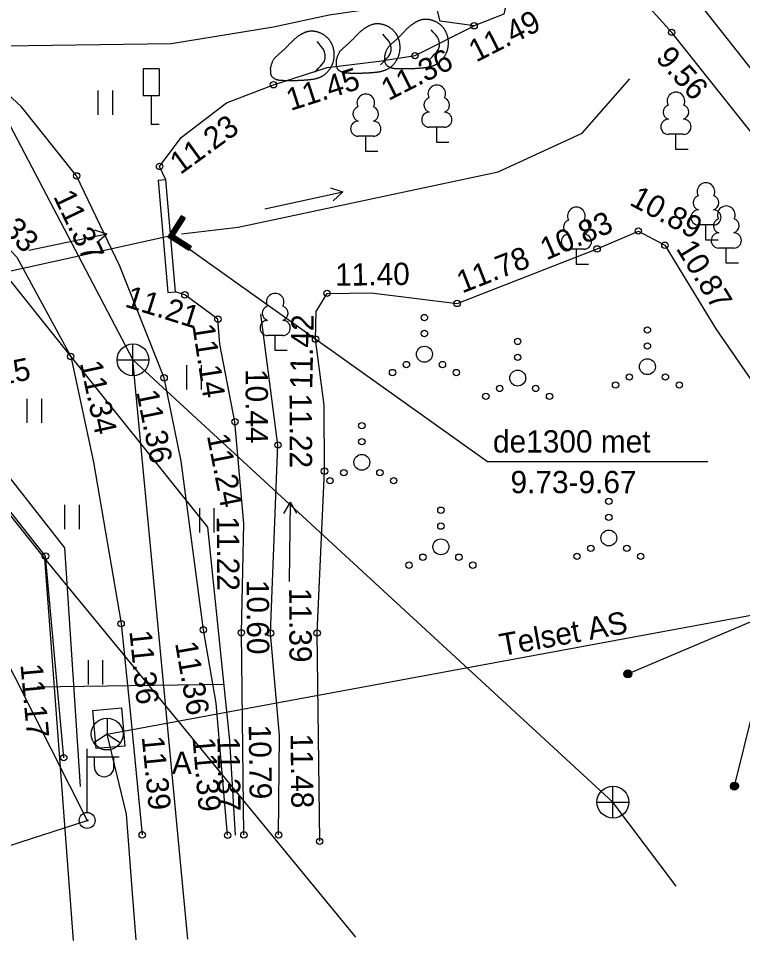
# Model space of a CAD drawing. Extents: x 554198 to 554371, y 6593448 to 6593563.
# Drawn here: x 554259.39 to 554282.11, y 6593473.51 to 6593502.46 of the extents above; entities that cross this region are included whole.
import ezdxf

# ---------------------------------------------------------------- set-up
doc = ezdxf.new("R2010")
doc.units = 0
for name, color, linetype in [('AED', 7, 'Continuous'), ('HALJASTUS', 7, 'Continuous'), ('KKAEV', 7, 'Continuous'), ('KORGUS-EH2000', 7, 'Continuous'), ('KTRASS', 7, 'Continuous'), ('LIIKLUS', 7, 'Continuous'), ('MPOHULIIN', 7, 'Continuous'), ('PIIR', 7, 'Continuous'), ('POST', 7, 'Continuous'), ('PUU', 7, 'Continuous'), ('RELJEEF', 7, 'Continuous'), ('SIKAEV', 7, 'Continuous'), ('SITRASS', 7, 'Continuous'), ('TEE', 7, 'Continuous'), ('TRUUP', 7, 'Continuous'), ('VEEKOGU', 7, 'Continuous'), ('VTRASS', 7, 'Continuous')]:
    doc.layers.add(name, color=color, linetype=linetype)

msp = doc.modelspace()

# ---------------------------------------------------------------- linework, layer by layer
at = {"layer": 'AED'}
msp.add_lwpolyline([(554260.808, 6593479.255), (554260.236, 6593485.581), (554256.809, 6593489.922), (554255.799, 6593491.136), (554253.28, 6593490.558), (554237.91, 6593487.208)], dxfattribs=at)
at = {"layer": 'HALJASTUS'}
for p, q in [((554261.882, 6593500.196), (554261.882, 6593499.435)), ((554262.337, 6593500.196), (554262.337, 6593499.435)), ((554264.664, 6593491.571), (554264.664, 6593490.81)), ((554265.119, 6593491.571), (554265.119, 6593490.81)), ((554259.652, 6593490.523), (554259.652, 6593489.761)), ((554260.107, 6593490.523), (554260.107, 6593489.761)), ((554260.837, 6593487.189), (554260.837, 6593486.428)), ((554261.292, 6593487.189), (554261.292, 6593486.428)), ((554265.065, 6593487.083), (554265.065, 6593486.321)), ((554265.52, 6593487.083), (554265.52, 6593486.321)), ((554261.57, 6593482.312), (554261.57, 6593481.551)), ((554262.025, 6593482.312), (554262.025, 6593481.551))]:
    msp.add_line(p, q, dxfattribs=at)
msp.add_lwpolyline([(554257.157, 6593490.52), (554260.832, 6593485.839), (554261.325, 6593478.347)], dxfattribs=at)
for centre, radius in [((554272.125, 6593493.069), 0.1), ((554272.125, 6593492.569), 0.1), ((554279.122, 6593492.678), 0.1), ((554275.052, 6593492.321), 0.1), ((554272.125, 6593491.919), 0.25), ((554279.122, 6593492.178), 0.1), ((554275.052, 6593491.821), 0.1), ((554279.122, 6593491.528), 0.25), ((554271.125, 6593491.344), 0.1), ((554271.56, 6593491.594), 0.1), ((554272.69, 6593491.594), 0.1), ((554273.125, 6593491.344), 0.1), ((554275.052, 6593491.171), 0.25), ((554278.557, 6593491.203), 0.1), ((554279.687, 6593491.203), 0.1), ((554274.487, 6593490.846), 0.1), ((554275.617, 6593490.846), 0.1), ((554278.122, 6593490.953), 0.1), ((554280.122, 6593490.953), 0.1), ((554274.052, 6593490.596), 0.1), ((554276.052, 6593490.596), 0.1), ((554270.162, 6593489.676), 0.1), ((554270.162, 6593489.176), 0.1), ((554270.162, 6593488.526), 0.25), ((554269.597, 6593488.201), 0.1), ((554270.727, 6593488.201), 0.1), ((554269.162, 6593487.951), 0.1), ((554271.162, 6593487.951), 0.1), ((554277.912, 6593487.301), 0.1), ((554272.642, 6593487.023), 0.1), ((554277.912, 6593486.801), 0.1), ((554272.642, 6593486.523), 0.1), ((554277.912, 6593486.151), 0.25), ((554272.642, 6593485.873), 0.25), ((554277.347, 6593485.826), 0.1), ((554278.477, 6593485.826), 0.1), ((554272.077, 6593485.548), 0.1), ((554273.207, 6593485.548), 0.1), ((554276.912, 6593485.576), 0.1), ((554278.912, 6593485.576), 0.1), ((554271.642, 6593485.298), 0.1), ((554273.642, 6593485.298), 0.1)]:
    msp.add_circle(centre, radius, dxfattribs=at)
at = {"layer": 'KKAEV'}
for p, q in [((554262.98, 6593491.24), (554262.98, 6593492.24)), ((554262.48, 6593491.74), (554263.48, 6593491.74)), ((554278.04, 6593477.36), (554278.04, 6593478.36)), ((554277.54, 6593477.86), (554278.54, 6593477.86))]:
    msp.add_line(p, q, dxfattribs=at)
for centre in [(554262.98, 6593491.74), (554278.04, 6593477.86)]:
    msp.add_circle(centre, 0.5, dxfattribs=at)
at = {"layer": 'KORGUS-EH2000'}
for centre in [(554273.684, 6593502.229), (554279.884, 6593502.023), (554271.831, 6593501.292), (554267.388, 6593500.378), (554263.816, 6593497.814), (554261.213, 6593497.518), (554278.839, 6593495.787), (554277.543, 6593495.225), (554279.67, 6593495.34), (554264.61, 6593493.783), (554269.07, 6593493.83), (554273.152, 6593493.512), (554265.646, 6593493.019), (554268.71, 6593492.39), (554261.027, 6593491.848), (554263.957, 6593491.18), (554266.18, 6593489.8), (554267.53, 6593489.07), (554268.99, 6593488.25), (554260.236, 6593485.581), (554262.608, 6593483.462), (554265.19, 6593483.27), (554266.381, 6593483.176), (554267.298, 6593483.162), (554268.76, 6593483.17), (554260.808, 6593479.255), (554263.27, 6593476.83), (554265.95, 6593476.82), (554266.46, 6593476.83), (554267.55, 6593476.83), (554268.84, 6593476.63)]:
    msp.add_circle(centre, 0.1, dxfattribs=at)
at = {"layer": 'KTRASS'}
for points in [[(554255.375, 6593506.25), (554262.98, 6593491.74)], [(554264.698, 6593473.559), (554262.98, 6593491.74)], [(554262.98, 6593491.74), (554278.04, 6593477.86)], [(554280.029, 6593475.225), (554278.04, 6593477.86)]]:
    msp.add_lwpolyline(points, dxfattribs=at)
at = {"layer": 'LIIKLUS'}
for points in [[(554263.305, 6593500.88), (554263.305, 6593500.03)], [(554263.805, 6593500.88), (554263.305, 6593500.88)], [(554263.805, 6593500.88), (554263.805, 6593500.03)], [(554263.805, 6593500.03), (554263.305, 6593500.03)], [(554263.555, 6593500.03), (554263.555, 6593499.13)], [(554263.805, 6593499.13), (554263.555, 6593499.13)]]:
    msp.add_lwpolyline(points, dxfattribs=at)
at = {"layer": 'MPOHULIIN'}
msp.add_lwpolyline([(554248.452, 6593503.231), (554261.544, 6593477.284)], dxfattribs=at)
at = {"layer": 'PIIR'}
for p, q in [((554294.582, 6593485.373), (554263.353, 6593525.033)), ((554255.79, 6593491.05), (554260.2, 6593485.51)), ((554260.2, 6593485.51), (554261.101, 6593473.514)), ((554260.2, 6593485.51), (554269.962, 6593473.624))]:
    msp.add_line(p, q, dxfattribs=at)
at = {"layer": 'POST'}
for p, q in [((554278.509, 6593481.885), (554283.22, 6593483.889)), ((554281.851, 6593478.362), (554283.22, 6593483.889)), ((554261.544, 6593477.534), (554261.544, 6593479.534)), ((554261.544, 6593479.284), (554262.544, 6593479.284)), ((554261.771, 6593478.963), (554261.771, 6593479.284)), ((554262.384, 6593478.963), (554262.384, 6593479.284)), ((554258.426, 6593476.274), (554261.544, 6593477.284))]:
    msp.add_line(p, q, dxfattribs=at)
for centre, radius in [((554278.509, 6593481.885), 0.125), ((554278.509, 6593481.885), 0.117), ((554278.509, 6593481.885), 0.109), ((554278.509, 6593481.885), 0.102), ((554278.509, 6593481.885), 0.0938), ((554278.509, 6593481.885), 0.086), ((554278.509, 6593481.885), 0.0782), ((554278.509, 6593481.885), 0.0704), ((554278.509, 6593481.885), 0.0626), ((554278.509, 6593481.885), 0.0548), ((554278.509, 6593481.885), 0.047), ((554278.509, 6593481.885), 0.0392), ((554278.509, 6593481.885), 0.0314), ((554278.509, 6593481.885), 0.0236), ((554278.509, 6593481.885), 0.0158), ((554278.509, 6593481.885), 0.00798), ((554278.509, 6593481.885), 0.000186), ((554281.851, 6593478.362), 0.125), ((554281.851, 6593478.362), 0.117), ((554281.851, 6593478.362), 0.109), ((554281.851, 6593478.362), 0.102), ((554281.851, 6593478.362), 0.0938), ((554281.851, 6593478.362), 0.086), ((554281.851, 6593478.362), 0.0782), ((554281.851, 6593478.362), 0.0704), ((554281.851, 6593478.362), 0.0626), ((554281.851, 6593478.362), 0.0548), ((554281.851, 6593478.362), 0.047), ((554281.851, 6593478.362), 0.0392), ((554281.851, 6593478.362), 0.0314), ((554281.851, 6593478.362), 0.0236), ((554281.851, 6593478.362), 0.0158), ((554281.851, 6593478.362), 0.00798), ((554281.851, 6593478.362), 0.000186), ((554261.544, 6593477.284), 0.25), ((554261.544, 6593477.284), 0.0234)]:
    msp.add_circle(centre, radius, dxfattribs=at)
msp.add_arc((554262.077, 6593478.963), 0.306, 180, 0, dxfattribs=at)
at = {"layer": 'PUU'}
for p, q in [((554272.754, 6593499.045), (554272.274, 6593499.045)), ((554272.514, 6593498.57), (554272.514, 6593499.045)), ((554270.526, 6593498.762), (554270.046, 6593498.762)), ((554270.286, 6593498.287), (554270.286, 6593498.762)), ((554280.257, 6593498.822), (554279.777, 6593498.822)), ((554280.017, 6593498.347), (554280.017, 6593498.822)), ((554272.894, 6593498.57), (554272.514, 6593498.57)), ((554270.666, 6593498.287), (554270.286, 6593498.287)), ((554280.397, 6593498.347), (554280.017, 6593498.347)), ((554281.199, 6593495.977), (554280.719, 6593495.977)), ((554280.959, 6593495.502), (554280.959, 6593495.977)), ((554281.339, 6593495.502), (554280.959, 6593495.502)), ((554277.133, 6593495.214), (554276.653, 6593495.214)), ((554276.893, 6593494.739), (554276.893, 6593495.214)), ((554281.838, 6593495.252), (554281.358, 6593495.252)), ((554281.598, 6593494.777), (554281.598, 6593495.252)), ((554277.273, 6593494.739), (554276.893, 6593494.739)), ((554281.978, 6593494.777), (554281.598, 6593494.777)), ((554267.682, 6593492.507), (554267.202, 6593492.507)), ((554267.442, 6593492.032), (554267.442, 6593492.507)), ((554267.822, 6593492.032), (554267.442, 6593492.032))]:
    msp.add_line(p, q, dxfattribs=at)
for centre, radius, start, end in [((554272.514, 6593500.09), 0.277, 332.5799, 207.4201), ((554280.017, 6593499.867), 0.277, 332.5799, 207.4201), ((554270.286, 6593499.807), 0.277, 332.5799, 207.4201), ((554272.344, 6593499.743), 0.233, 109.0217, 253.1415), ((554272.684, 6593499.743), 0.233, 286.8508, 70.9859), ((554270.116, 6593499.46), 0.233, 109.0217, 253.1415), ((554270.456, 6593499.46), 0.233, 286.8508, 70.9859), ((554272.277, 6593499.282), 0.238, 90.0016, 269.3953), ((554272.751, 6593499.282), 0.238, 270.6047, 89.9984), ((554279.847, 6593499.52), 0.233, 109.0217, 253.1415), ((554280.187, 6593499.52), 0.233, 286.8508, 70.9859), ((554270.049, 6593498.999), 0.238, 90.0016, 269.3953), ((554270.523, 6593498.999), 0.238, 270.6047, 89.9984), ((554279.78, 6593499.059), 0.238, 90.0016, 269.3953), ((554280.254, 6593499.059), 0.238, 270.6047, 89.9984), ((554280.959, 6593497.022), 0.277, 332.5799, 207.4201), ((554280.789, 6593496.675), 0.233, 109.0217, 253.1415), ((554281.129, 6593496.675), 0.233, 286.8508, 70.9859), ((554276.893, 6593496.259), 0.277, 332.5799, 207.4201), ((554280.722, 6593496.214), 0.238, 90.0016, 269.3953), ((554281.196, 6593496.214), 0.238, 270.6047, 89.9984), ((554281.598, 6593496.297), 0.277, 332.5799, 207.4201), ((554276.723, 6593495.912), 0.233, 109.0217, 253.1415), ((554277.063, 6593495.912), 0.233, 286.8508, 70.9859), ((554281.428, 6593495.95), 0.233, 109.0217, 253.1415), ((554281.768, 6593495.95), 0.233, 286.8508, 70.9859), ((554276.656, 6593495.451), 0.238, 90.0016, 269.3953), ((554277.13, 6593495.451), 0.238, 270.6047, 89.9984), ((554281.361, 6593495.489), 0.238, 90.0016, 269.3953), ((554281.835, 6593495.489), 0.238, 270.6047, 89.9984), ((554267.442, 6593493.552), 0.277, 332.5799, 207.4201), ((554267.272, 6593493.205), 0.233, 109.0217, 253.1415), ((554267.612, 6593493.205), 0.233, 286.8508, 70.9859), ((554267.205, 6593492.744), 0.238, 90.0016, 269.3953), ((554267.679, 6593492.744), 0.238, 270.6047, 89.9984)]:
    msp.add_arc(centre, radius, start, end, dxfattribs=at)
at = {"layer": 'RELJEEF'}
for points in [[(554270.75, 6593501.004), (554270.793, 6593501.049), (554270.861, 6593501.122), (554270.929, 6593501.196), (554270.997, 6593501.269), (554271.053, 6593501.351), (554271.078, 6593501.448), (554271.078, 6593501.547), (554271.057, 6593501.645), (554271.015, 6593501.735), (554270.952, 6593501.813), (554270.886, 6593501.888), (554270.82, 6593501.963)], [(554272.267, 6593501.145), (554272.31, 6593501.19), (554272.378, 6593501.263), (554272.446, 6593501.337), (554272.514, 6593501.41), (554272.57, 6593501.492), (554272.595, 6593501.589), (554272.595, 6593501.688), (554272.574, 6593501.786), (554272.532, 6593501.876), (554272.469, 6593501.954), (554272.403, 6593502.029), (554272.337, 6593502.104)], [(554268.685, 6593500.773), (554268.728, 6593500.818), (554268.796, 6593500.891), (554268.864, 6593500.965), (554268.932, 6593501.038), (554268.988, 6593501.12), (554269.013, 6593501.217), (554269.013, 6593501.316), (554268.992, 6593501.414), (554268.95, 6593501.504), (554268.887, 6593501.582), (554268.821, 6593501.657), (554268.755, 6593501.732)]]:
    msp.add_lwpolyline(points, dxfattribs=at)
for points in [[(554270.882, 6593501.275), (554270.882, 6593501.275), (554270.887, 6593501.016), (554271.081, 6593500.887), (554271.33, 6593500.875), (554271.58, 6593500.874), (554271.83, 6593500.881), (554272.08, 6593500.899), (554272.327, 6593500.934), (554272.553, 6593501.037), (554272.728, 6593501.213), (554272.842, 6593501.435), (554272.877, 6593501.681), (554272.847, 6593501.929), (554272.74, 6593502.153), (554272.56, 6593502.325), (554272.334, 6593502.429), (554272.087, 6593502.448), (554271.856, 6593502.354), (554271.652, 6593502.21), (554271.478, 6593502.031), (554271.305, 6593501.85), (554271.117, 6593501.687), (554270.935, 6593501.518), (554270.882, 6593501.275)], [(554269.365, 6593501.134), (554269.365, 6593501.134), (554269.37, 6593500.875), (554269.564, 6593500.746), (554269.813, 6593500.734), (554270.063, 6593500.733), (554270.313, 6593500.74), (554270.563, 6593500.758), (554270.81, 6593500.793), (554271.036, 6593500.896), (554271.211, 6593501.072), (554271.325, 6593501.294), (554271.36, 6593501.54), (554271.33, 6593501.788), (554271.223, 6593502.012), (554271.043, 6593502.184), (554270.817, 6593502.288), (554270.57, 6593502.307), (554270.339, 6593502.213), (554270.135, 6593502.069), (554269.961, 6593501.89), (554269.788, 6593501.709), (554269.6, 6593501.546), (554269.418, 6593501.377), (554269.365, 6593501.134)], [(554267.3, 6593500.903), (554267.3, 6593500.903), (554267.305, 6593500.644), (554267.499, 6593500.515), (554267.748, 6593500.503), (554267.998, 6593500.502), (554268.248, 6593500.509), (554268.498, 6593500.527), (554268.745, 6593500.562), (554268.971, 6593500.665), (554269.146, 6593500.841), (554269.26, 6593501.063), (554269.295, 6593501.309), (554269.265, 6593501.557), (554269.158, 6593501.781), (554268.978, 6593501.953), (554268.752, 6593502.057), (554268.505, 6593502.076), (554268.274, 6593501.982), (554268.07, 6593501.838), (554267.896, 6593501.659), (554267.723, 6593501.478), (554267.535, 6593501.315), (554267.353, 6593501.146), (554267.3, 6593500.903)]]:
    msp.add_open_spline(points, degree=2, dxfattribs=at)
at = {"layer": 'SIKAEV'}
for p, q in [((554262.169, 6593480.496), (554262.169, 6593479.996)), ((554262.169, 6593479.996), (554261.754, 6593479.721)), ((554262.169, 6593479.996), (554262.584, 6593479.721))]:
    msp.add_line(p, q, dxfattribs=at)
msp.add_lwpolyline([(554262.621, 6593480.817), (554262.724, 6593479.621), (554261.828, 6593479.544), (554261.724, 6593480.739)], close=True, dxfattribs=at)
msp.add_circle((554262.169, 6593479.996), 0.5, dxfattribs=at)
at = {"layer": 'SITRASS'}
for points in [[(554262.169, 6593479.996), (554283.22, 6593483.889)], [(554263.08, 6593473.539), (554262.969, 6593475.007), (554262.782, 6593477.484), (554262.169, 6593479.996)]]:
    msp.add_lwpolyline(points, dxfattribs=at)
at = {"layer": 'TEE'}
msp.add_lwpolyline([(554274.579, 6593502.878), (554274.655, 6593502.782), (554274.616, 6593502.597), (554273.684, 6593502.229), (554272.617, 6593502.372), (554272.497, 6593502.867), (554272.745, 6593503.98), (554273.284, 6593503.965), (554273.992, 6593503.859), (554274.044, 6593503.92), (554274.534, 6593502.939)], close=True, dxfattribs=at)
for points in [[(554272.497, 6593502.867), (554270.945, 6593502.819), (554269.137, 6593502.567), (554267.385, 6593502.182), (554264.175, 6593501.658), (554257.446, 6593501.567)], [(554265.95, 6593476.82), (554265.59, 6593480.97), (554265.19, 6593483.27), (554264.491, 6593488.567), (554263.957, 6593491.18), (554262.564, 6593494.685), (554261.213, 6593497.518), (554259.482, 6593499.687), (554257.446, 6593501.567), (554254.616, 6593502.167), (554251.838, 6593502.198), (554248.68, 6593501.69), (554243.61, 6593500.842), (554237.947, 6593499.485), (554232.294, 6593498.32)], [(554233.4, 6593494.02), (554238.185, 6593494.981), (554244.645, 6593496.737), (554253.238, 6593498.179), (554255.093, 6593497.886), (554257.609, 6593496.774), (554259.336, 6593494.97), (554261.027, 6593491.848), (554261.746, 6593488.526), (554262.608, 6593483.462), (554262.89, 6593480.7), (554263.27, 6593476.83)]]:
    msp.add_lwpolyline(points, dxfattribs=at)
at = {"layer": 'TRUUP'}
for p, q in [((554264.493, 6593496.265), (554264.074, 6593495.609)), ((554264.553, 6593496.227), (554264.172, 6593495.631)), ((554264.524, 6593496.05), (554264.252, 6593495.888)), ((554264.613, 6593496.189), (554264.27, 6593495.653)), ((554264.554, 6593496.097), (554264.282, 6593495.935)), ((554264.584, 6593496.143), (554264.312, 6593495.982)), ((554264.612, 6593496.189), (554264.342, 6593496.029)), ((554264.588, 6593496.204), (554264.372, 6593496.076)), ((554264.565, 6593496.219), (554264.402, 6593496.122)), ((554264.541, 6593496.234), (554264.431, 6593496.169)), ((554264.517, 6593496.249), (554264.461, 6593496.216)), ((554264.613, 6593496.189), (554264.493, 6593496.265)), ((554261.764, 6593495.827), (554262.157, 6593495.699)), ((554264.345, 6593495.769), (554264.075, 6593495.609)), ((554264.374, 6593495.816), (554264.102, 6593495.654)), ((554264.404, 6593495.863), (554264.132, 6593495.701)), ((554264.434, 6593495.909), (554264.162, 6593495.748)), ((554264.464, 6593495.956), (554264.192, 6593495.795)), ((554264.494, 6593496.003), (554264.222, 6593495.842)), ((554259.711, 6593495.182), (554262.157, 6593495.699)), ((554261.849, 6593495.423), (554262.157, 6593495.699)), ((554264.074, 6593495.609), (554264.73, 6593495.19)), ((554264.315, 6593495.722), (554264.098, 6593495.594)), ((554264.285, 6593495.675), (554264.122, 6593495.579)), ((554264.283, 6593495.645), (554264.145, 6593495.564)), ((554264.306, 6593495.63), (554264.169, 6593495.548)), ((554264.172, 6593495.631), (554264.768, 6593495.25)), ((554264.33, 6593495.615), (554264.193, 6593495.533)), ((554264.353, 6593495.6), (554264.216, 6593495.518)), ((554264.377, 6593495.585), (554264.24, 6593495.503)), ((554264.4, 6593495.57), (554264.263, 6593495.488)), ((554264.27, 6593495.653), (554264.806, 6593495.31)), ((554264.424, 6593495.554), (554264.287, 6593495.473)), ((554264.448, 6593495.539), (554264.311, 6593495.458)), ((554264.471, 6593495.524), (554264.334, 6593495.443)), ((554264.495, 6593495.509), (554264.358, 6593495.428)), ((554264.518, 6593495.494), (554264.381, 6593495.413)), ((554264.542, 6593495.479), (554264.405, 6593495.398)), ((554264.566, 6593495.464), (554264.429, 6593495.383)), ((554264.589, 6593495.449), (554264.452, 6593495.368)), ((554264.613, 6593495.434), (554264.476, 6593495.353)), ((554264.636, 6593495.419), (554264.499, 6593495.337)), ((554264.66, 6593495.404), (554264.523, 6593495.322)), ((554264.684, 6593495.389), (554264.546, 6593495.307)), ((554264.707, 6593495.374), (554264.57, 6593495.292)), ((554264.731, 6593495.358), (554264.594, 6593495.277)), ((554264.754, 6593495.343), (554264.617, 6593495.262)), ((554264.778, 6593495.328), (554264.641, 6593495.247)), ((554264.802, 6593495.313), (554264.664, 6593495.232)), ((554264.782, 6593495.273), (554264.688, 6593495.217)), ((554264.752, 6593495.226), (554264.712, 6593495.202)), ((554264.806, 6593495.31), (554264.73, 6593495.19))]:
    msp.add_line(p, q, dxfattribs=at)
msp.add_lwpolyline([(554263.776, 6593497.367), (554264.078, 6593493.854), (554264.317, 6593493.875), (554264.015, 6593497.388)], close=True, dxfattribs=at)
for points in [[(554264.172, 6593495.631), (554257.865, 6593494.241)], [(554264.172, 6593495.631), (554274.102, 6593488.547), (554281.013, 6593488.547)]]:
    msp.add_lwpolyline(points, dxfattribs=at)
at = {"layer": 'VEEKOGU'}
for p, q in [((554267.123, 6593496.488), (554269.567, 6593497.013)), ((554269.174, 6593497.14), (554269.567, 6593497.013)), ((554269.261, 6593496.735), (554269.567, 6593497.013)), ((554267.709, 6593486.924), (554267.919, 6593487.28)), ((554267.891, 6593484.78), (554267.919, 6593487.28)), ((554268.122, 6593486.92), (554267.919, 6593487.28))]:
    msp.add_line(p, q, dxfattribs=at)
for points in [[(554289.699, 6593489.692), (554285.677, 6593494.745), (554279.884, 6593502.023), (554278.226, 6593503.871), (554276.897, 6593505.887), (554273.851, 6593510.088), (554268.23, 6593517.601), (554267.552, 6593518.507)], [(554264.015, 6593497.388), (554263.816, 6593497.814), (554264.497, 6593498.722), (554265.916, 6593499.806), (554267.388, 6593500.378), (554269.073, 6593500.918), (554270.705, 6593501.122), (554271.831, 6593501.292), (554273.684, 6593502.229)], [(554264.507, 6593495.699), (554266.281, 6593495.908), (554274.442, 6593497.645), (554277.072, 6593498.859), (554278.567, 6593500.564)], [(554268.84, 6593476.63), (554268.76, 6593483.17), (554268.99, 6593488.25), (554268.98, 6593490.32), (554268.71, 6593492.39), (554268.728, 6593493.256), (554269.07, 6593493.83), (554270.451, 6593493.847), (554273.152, 6593493.512), (554277.543, 6593495.225), (554278.839, 6593495.787), (554279.67, 6593495.34), (554281.27, 6593492.72), (554283.81, 6593489.03), (554286.14, 6593487.01)], [(554266.46, 6593476.83), (554266.381, 6593483.176), (554266.46, 6593486.61), (554266.18, 6593489.8), (554265.706, 6593492.235), (554265.646, 6593493.019), (554264.61, 6593493.783), (554264.317, 6593493.875)], [(554267.55, 6593476.83), (554267.58, 6593479.95), (554267.298, 6593483.162), (554267.53, 6593489.07), (554266.991, 6593493.177)]]:
    msp.add_lwpolyline(points, dxfattribs=at)
at = {"layer": 'VTRASS'}
for points in [[(554260.701, 6593492.276), (554252.41, 6593502.64), (554244.08, 6593513.051)], [(554266.196, 6593476.825), (554266.02, 6593479.79), (554265.33, 6593486.49), (554260.701, 6593492.276)], [(554259.975, 6593481.476), (554265.837, 6593481.564)]]:
    msp.add_lwpolyline(points, dxfattribs=at)

# ---------------------------------------------------------------- texts
at = {"layer": 'KORGUS-EH2000'}
for s, rotation, p in [(' 11.49 ', 26.8242, (554273.515, 6593500.955)), (' 9.56 ', 311.898, (554279.177, 6593501.389)), (' 11.36 ', 26.8242, (554270.763, 6593499.746)), (' 11.45 ', 17.7693, (554267.678, 6593499.473)), (' 11.23 ', 36.0274, (554264.256, 6593497.385)), (' 11.33 ', 313.7508, (554257.778, 6593496.935)), (' 11.37 ', 295.4955, (554260.356, 6593497.109)), (' 10.89 ', 331.7239, (554278.299, 6593496.746)), (' 10.83 ', 23.4436, (554275.713, 6593494.756)), (' 10.87 ', 301.4119, (554279.869, 6593495.462)), (' 11.78 ', 21.3116, (554273.067, 6593493.729)), (' 11.40 ', 0.7053, (554269.067, 6593494.063)), (' 11.21 ', 342.5681, (554262.447, 6593493.499)), (' 11.42 ', 88.8093, (554268.601, 6593490.56)), (' 11.14 ', 278.593, (554264.801, 6593493.084)), (' 11.25 ', 11.4066, (554257.261, 6593490.622)), (' 11.34 ', 282.2125, (554261.255, 6593491.897)), (' 10.44 ', 270.2768, (554266.51, 6593491.714)), (' 11.36 ', 281.5501, (554263.026, 6593490.99)), (' 11.22 ', 270.2768, (554267.89, 6593490.945)), (' 11.24 ', 281.0155, (554265.248, 6593489.618)), (' 11.22 ', 270.4029, (554265.606, 6593487.092)), (' 10.60 ', 270.2768, (554266.546, 6593485.096)), (' 11.39 ', 270.2768, (554267.879, 6593484.843)), (' 11.36 ', 275.8297, (554262.84, 6593483.486)), (' 11.36 ', 279.8658, (554264.254, 6593483.107)), (' 11.17 ', 275.1667, (554259.425, 6593482.439)), (' 10.79 ', 270.7008, (554266.609, 6593480.546)), (' 11.39 ', 275.608, (554263.229, 6593480.167)), (' 11.37 ', 270.7132, (554265.627, 6593480.172)), (' 11.48 ', 270.7008, (554267.92, 6593480.265)), (' 11.39 ', 274.9578, (554264.826, 6593480.125))]:
    msp.add_text(s, height=0.7, rotation=rotation, dxfattribs=at).set_placement(p)
at = {"layer": 'SITRASS'}
msp.add_text('Telset AS', height=0.7, rotation=10.411, dxfattribs=at).set_placement((554274.551, 6593482.441))
at = {"layer": 'TEE'}
msp.add_text('A', height=0.7, dxfattribs=at).set_placement((554264.2, 6593478.745))
at = {"layer": 'TRUUP'}
for s, p in [('de1300 met', (554274.276, 6593488.833)), ('9.73-9.67', (554274.826, 6593487.557))]:
    msp.add_text(s, height=0.7, dxfattribs=at).set_placement(p)

doc.saveas('drawing.dxf')
